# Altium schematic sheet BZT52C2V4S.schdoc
size 127 x 101 mm
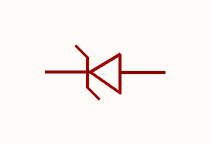
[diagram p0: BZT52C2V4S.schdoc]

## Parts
ZD?  bzt52c2v4s_c17285  [SOD-323_L1.8-W1.3-LS2.5-RD]  (value not drawn)

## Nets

Not connected (* = marked no-connect by the designer): ZD? 1(K) 2(A)

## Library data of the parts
ZD? = bzt52c2v4s_c17285: 二极管配置:1个独立式;稳压值(标称值):2.4V;稳压值(范围):2.2V~2.6V;耗散功率(Pd):200mW;; Manufacturer: CJ(江苏长电/长晶); AddInBom: yes; ModelId: db63db13d9e342eb939127d413d6200b; ModelTransform: 104.3305,51.181,0,0,0,0,0,-0.004,0; Diode Configuration: 1个独立式; Zener Voltage(Nom): 2.4V; Reverse Leakage Current (Ir): 50uA; Pd - Power Dissipation: 200mW; Impedance(Zzt): 100Ω; Impedance(Zzk): 600Ω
